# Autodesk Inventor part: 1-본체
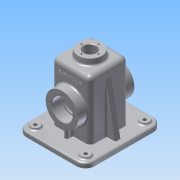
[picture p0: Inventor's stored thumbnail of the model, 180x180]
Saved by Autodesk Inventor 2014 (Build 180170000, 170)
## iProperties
Created: 2016-06
Part Number: 1-본체
Material: 알루미늄 6061
Document SubType Name: Modeling
Designer: Administrator
Density: 2.71 g/cm^3
Appearance: 알루미늄 - 평지
Mass: 812.786 g
Surface Area: 906.873 cm^2
Volume: 299.921 cm^3
Author: Administrator
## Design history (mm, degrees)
sketch "스케치1"
  geometry: L1 (57.5, -65)-(-57.5, -65); L2 (-57.5, -65)-(-57.5, 65); L3 (-57.5, 65)-(57.5, 65); L4 (57.5, 65)-(57.5, -65); L5 (57.5, -65)-(-57.5, 65); L6 (-57.5, -65)-(57.5, 65); 3 further points
  constraints: 12 end point, 3 midpoint, 2 parallel, 1 coincident, 1 horizontal, 1 perpendicular
  dimensions: "d0" = 115 distance of L2.end L3.end; "d1" = 130 distance of L1.end L2.end
extrude "돌출1" new body sketch "스케치1" distance "d2" = 8; taper "d3" = 0 deg
sketch "스케치2"
  geometry: L1 (52.5, 60)-(-52.5, 60); L2 (-52.5, 60)-(-52.5, -60); L3 (-52.5, -60)-(52.5, -60); L4 (52.5, -60)-(52.5, 60); L5 (52.5, 60)-(-52.5, -60); L6 (-52.5, 60)-(52.5, -60); 1 further point
  constraints: 12 end point, 2 midpoint, 2 parallel, 1 horizontal, 1 perpendicular
  dimensions: "d4" = 105 distance of L3.end L2.end; "d5" = 120 distance of L2.end L1.end
extrude "돌출2" join sketch "스케치2" distance "d6" = 2; taper "d7" = 0 deg
fillet "모깎기1" dims "d8" = 15, "d9" = 10
sketch "스케치3"
  geometry: L1 (32.5, 32.5)-(-32.5, 32.5); L2 (-32.5, 32.5)-(-32.5, -32.5); L3 (-32.5, -32.5)-(32.5, -32.5); L4 (32.5, -32.5)-(32.5, 32.5); L5 (32.5, 32.5)-(-32.5, -32.5); L6 (-32.5, 32.5)-(32.5, -32.5); 1 further point
  constraints: 12 end point, 2 midpoint, 2 parallel, 1 horizontal, 1 perpendicular
  dimensions: "d10" = 65 distance of L3.end L2.end; "d11" = 65 distance of L2.end L1.end
extrude "돌출3" join sketch "스케치3" distance "d12" = 100; taper "d13" = 0 deg
node "작업 평면1"
sketch "스케치5"
  geometry: C1 r 20 at (0, 0); 1 further point
  constraints: 1 centre point, 1 coincident
  dimensions: "d16" = 40 diameter of C1
extrude "돌출4" join sketch "스케치5" distance "d17" = 10; taper "d18" = 5 deg
sketch "스케치7"
  geometry: L1 (27.5, 27.5)-(-27.5, 27.5); L2 (-27.5, 27.5)-(-27.5, -27.5); L3 (-27.5, -27.5)-(27.5, -27.5); L4 (27.5, -27.5)-(27.5, 27.5); L5 (27.5, 27.5)-(-27.5, -27.5); L6 (-27.5, 27.5)-(27.5, -27.5); 3 further points
  constraints: 12 end point, 3 midpoint, 2 parallel, 1 coincident, 1 horizontal, 1 perpendicular
  dimensions: "d19" = 55 distance of L3.end L2.end; "d20" = 55 distance of L2.end L1.end
extrude "돌출5" cut sketch "스케치7" distance "d21" = 105; taper "d22" = 0 deg
sketch "스케치9"
  geometry: C1 r 7.5 at (-42.5, 50); A1 r 15 centre (-42.5, 50) between (-42.5, 65) and (-57.5, 50) reference; 1 further point
  constraints: 1 centre point, 1 coincident
  dimensions: "d23" = 15 diameter of C1
extrude "돌출6" join sketch "스케치9" distance "d24" = 3; taper "d25" = 0 deg
sketch "스케치10"
  geometry: C1 r 7.5 at (0, 0) reference; C2 r 3 at (0, 0); 1 further point
  constraints: 1 centre point, 1 coincident
  dimensions: "d26" = 6 diameter of C2
extrude "돌출7" cut sketch "스케치10" distance "d27" = 20; taper "d28" = 0 deg
fillet "모깎기2" dims "d29" = 3
fillet "모깎기3" dims "d37" = 3, "d73" = 3, "d74" = 3
sketch "스케치12"
  geometry: L1 (0, 100)-(65, 100) reference; L2 (85, -10)-(75, -10) reference; C1 r 27.5 at (32.5, 45); 2 further points
  constraints: 1 centre point, 1 midpoint, 1 vertical alignment
  dimensions: "d40" = 55 diameter of C1; "d41" = 55 distance from line of L2 C1.centre
extrude "돌출8" join sketch "스케치12" distance "d42" = 15; taper "d43" = 0 deg
hole "구멍1" diameter "d46" = 30; stored, may be unused: countersink angle "d50" = 90 deg, drill point angle "d52" = 118 deg; dims "d44" = 10, "d45" = 10, "d47" = 6, "d48" = 35, "d49" = 17, "d51" = 20
sketch "스케치14"
  geometry: C1 r 17.5 at (0, 0) reference; 2 further points
  constraints: 1 vertical alignment
  dimensions: "d53" = 21 distance of C1.centre point (0, 21)
hole "구멍2" sketch "스케치14" at (0, 21) diameter "d54" = 3.242; stored, may be unused: countersink angle "d58" = 90 deg, drill point angle "d60" = 118 deg; dims "d55" = 8, "d56" = 35, "d57" = 17, "d59" = 10
chamfer "모따기1" distance "d64" = 1; stored, may be unused: second distance "d65" = 2, angle "d66" = 45 deg
fillet "모깎기4" dims "d67" = 0.3
fillet "모깎기5" dims "d68" = 8
fillet "모깎기6" dims "d69" = 3
fillet "모깎기7" dims "d70" = 8, "d71" = 3
fillet "모깎기8" dims "d72" = 8
sketch "스케치15"
  geometry: C1 r 20 at (0, 0) reference; C2 r 10.5 at (0, 0)
  constraints: 1 centre point, 1 coincident
  dimensions: "d75" = 21 diameter of C2
extrude "돌출9" cut sketch "스케치15" distance "d76" = 30; taper "d77" = 0 deg
sketch "스케치16"
  geometry: C1 r 10.5 at (0, 0) reference; 1 further point
  constraints: 1 vertical alignment
  dimensions: "d78" = 14.5 distance of C1.centre point (0, 14.5)
hole "구멍3" sketch "스케치16" at (0, 14.5) diameter "d79" = 2.459; stored, may be unused: countersink angle "d83" = 90 deg, drill point angle "d85" = 118 deg; dims "d80" = 7, "d81" = 35, "d82" = 17, "d84" = 9
sketch "스케치18"
  geometry: L1 (-27.5, 100)-(-27.5, -2) reference; L2 (-27.5, -2)-(-52.5, -2) reference; L3 (-52.5, -2)-(-52.5, 0) reference; L4 (-52.5, 0)-(-57.5, 0) reference; L5 (-57.5, 0)-(-57.5, 8) reference; L6 (-57.5, 8)-(-32.5, 8) reference; L7 (-32.5, 8)-(-32.5, 100) reference; L8 (-24.5, 108)-(-23.624, 108) reference; L9 (-20.635, 110.739)-(-20, 118) reference; L10 (-20, 118)-(-15.73, 118) reference; L11 (-15.73, 118)-(-15.73, 109) reference; L12 (-15.73, 109)-(-14.5, 108.261) reference; L13 (-14.5, 108.261)-(-13.271, 109) reference; L14 (-13.271, 109)-(-13.271, 118) reference; L15 (-13.271, 118)-(-10.5, 118) reference; L16 (-10.5, 118)-(-10.5, 103) reference; L17 (-10.5, 103)-(-24.5, 103) reference; L18 (24.5, 103)-(10.5, 103) reference; L19 (10.5, 103)-(10.5, 118) reference; L20 (10.5, 118)-(13.271, 118) reference; L21 (13.271, 118)-(13.271, 109) reference; L22 (13.271, 109)-(14.5, 108.261) reference; L23 (14.5, 108.261)-(15.73, 109) reference; L24 (15.73, 109)-(15.73, 118) reference; L25 (15.73, 118)-(20, 118) reference; L26 (20, 118)-(20.635, 110.739) reference; L27 (23.624, 108)-(24.5, 108) reference; L28 (32.5, 100)-(32.5, 8) reference; L29 (32.5, 8)-(57.5, 8) reference; L30 (57.5, 8)-(57.5, 0) reference; L31 (57.5, 0)-(52.5, 0) reference; L32 (52.5, 0)-(52.5, -2) reference; L33 (52.5, -2)-(27.5, -2) reference; L34 (27.5, -2)-(27.5, 100) reference; L35 (-32, 8)-(-53, 8) reference; L36 (-47.5, 8)-(-32.5, 93.069); L37 (-32.5, 8)-(-32.5, 100) reference; A1 r 3 centre (-24.5, 100) between (-24.5, 103) and (-27.5, 100) reference; A2 r 8 centre (-24.5, 100) between (-24.5, 108) and (-32.5, 100) reference; A3 r 3 centre (-23.624, 111) between (-23.624, 108) and (-20.635, 110.739) reference; A4 r 3 centre (24.5, 100) between (27.5, 100) and (24.5, 103) reference; A5 r 3 centre (23.624, 111) between (20.635, 110.739) and (23.624, 108) reference; A6 r 8 centre (24.5, 100) between (32.5, 100) and (24.5, 108) reference; 1 further point
  constraints: 2 end point, 2 point on line
  dimensions: "d95" = 10 distance from line of L5 L36.start; "d96" = 10 deg angle of L5 L36
extrude "돌출11" join sketch "스케치18" stored distance "d97" = 10; taper "d98" = 0 deg
sketch "스케치19"
  geometry: L1 (24.5, 103)-(10.5, 103) reference; L2 (10.5, 103)-(10.5, 118) reference; L3 (10.5, 118)-(13.271, 118) reference; L4 (13.271, 118)-(13.271, 109) reference; L5 (13.271, 109)-(14.5, 108.261) reference; L6 (14.5, 108.261)-(15.73, 109) reference; L7 (15.73, 109)-(15.73, 118) reference; L8 (15.73, 118)-(20, 118) reference; L9 (20, 118)-(20.635, 110.739) reference; L10 (23.624, 108)-(24.5, 108) reference; L11 (32.5, 100)-(32.5, 83.5) reference; L12 (35.5, 80.5)-(47.5, 80.5) reference; L13 (47.5, 80.5)-(47.5, 75.621) reference; L14 (47.5, 75.621)-(37.5, 75.621) reference; L15 (37.5, 75.621)-(36.526, 74) reference; L16 (36.526, 74)-(37.5, 72.379) reference; L17 (37.5, 72.379)-(47.5, 72.379) reference; L18 (47.5, 72.379)-(47.5, 71.5) reference; L19 (47.5, 71.5)-(46.5, 70.5) reference; L20 (46.5, 70.5)-(30.8, 70.5) reference; L21 (30.5, 70.2)-(30.5, 68) reference; L22 (30.5, 68)-(27.5, 68) reference; L23 (27.5, 68)-(27.5, 100) reference; L24 (-27.5, 100)-(-27.5, 68) reference; L25 (-27.5, 68)-(-30.5, 68) reference; L26 (-30.5, 68)-(-30.5, 70.2) reference; L27 (-30.8, 70.5)-(-46.5, 70.5) reference; L28 (-46.5, 70.5)-(-47.5, 71.5) reference; L29 (-47.5, 71.5)-(-47.5, 72.379) reference; L30 (-47.5, 72.379)-(-37.5, 72.379) reference; L31 (-37.5, 72.379)-(-36.526, 74) reference; L32 (-36.526, 74)-(-37.5, 75.621) reference; L33 (-37.5, 75.621)-(-47.5, 75.621) reference; L34 (-47.5, 75.621)-(-47.5, 80.5) reference; L35 (-47.5, 80.5)-(-35.5, 80.5) reference; L36 (-32.5, 83.5)-(-32.5, 100) reference; L37 (-24.5, 108)-(-23.624, 108) reference; L38 (-20.635, 110.739)-(-20, 118) reference; L39 (-20, 118)-(-15.73, 118) reference; L40 (-15.73, 118)-(-15.73, 109) reference; L41 (-15.73, 109)-(-14.5, 108.261) reference; L42 (-14.5, 108.261)-(-13.271, 109) reference; L43 (-13.271, 109)-(-13.271, 118) reference; L44 (-13.271, 118)-(-10.5, 118) reference; L45 (-10.5, 118)-(-10.5, 103) reference; L46 (-10.5, 103)-(-24.5, 103) reference; L47 (-60, -2)-(-60, 0) reference; L48 (-60, 0)-(-65, 0) reference; L49 (-65, 0)-(-65, 8) reference; L50 (-65, 8)-(-32.5, 8) reference; L51 (-32.5, 8)-(-32.5, 22.5) reference; L52 (-35.5, 25.5)-(-47.5, 25.5) reference; L53 (-47.5, 25.5)-(-47.5, 30.379) reference; L54 (-47.5, 30.379)-(-37.5, 30.379) reference; L55 (-37.5, 30.379)-(-36.526, 32) reference; L56 (-36.526, 32)-(-37.5, 33.621) reference; L57 (-37.5, 33.621)-(-47.5, 33.621) reference; L58 (-47.5, 33.621)-(-47.5, 34.5) reference; L59 (-47.5, 34.5)-(-46.5, 35.5) reference; L60 (-46.5, 35.5)-(-30.8, 35.5) reference; L61 (-30.5, 35.8)-(-30.5, 38) reference; L62 (-30.5, 38)-(-27.5, 38) reference; L63 (-27.5, 38)-(-27.5, -2) reference; L64 (-27.5, -2)-(-60, -2) reference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; A1 r 3 centre (24.5, 100) between (27.5, 100) and (24.5, 103) reference; A2 r 3 centre (23.624, 111) between (20.635, 110.739) and (23.624, 108) reference; A3 r 8 centre (24.5, 100) between (32.5, 100) and (24.5, 108) reference; A4 r 3 centre (35.5, 83.5) between (32.5, 83.5) and (35.5, 80.5) reference; A5 r 0.3 centre (30.8, 70.2) between (30.8, 70.5) and (30.5, 70.2) reference; A6 r 3 centre (-24.5, 100) between (-24.5, 103) and (-27.5, 100) reference; A7 r 0.3 centre (-30.8, 70.2) between (-30.5, 70.2) and (-30.8, 70.5) reference; A8 r 3 centre (-35.5, 83.5) between (-35.5, 80.5) and (-32.5, 83.5) reference; A9 r 8 centre (-24.5, 100) between (-24.5, 108) and (-32.5, 100) reference; A10 r 3 centre (-23.624, 111) between (-23.624, 108) and (-20.635, 110.739) reference; A11 r 3 centre (-35.5, 22.5) between (-32.5, 22.5) and (-35.5, 25.5) reference; A12 r 0.3 centre (-30.8, 35.8) between (-30.8, 35.5) and (-30.5, 35.8) reference; A13 r 0.3 centre (30.8, 35.8) between (30.5, 35.8) and (30.8, 35.5) reference; A14 r 3 centre (35.5, 22.5) between (35.5, 25.5) and (32.5, 22.5) reference; 1 further point
  constraints: 8 end point, 2 parallel, 1 collinear, 1 perpendicular, 1 point on line
  dimensions: "d99" = 20 distance of L84.end L50.end; "d101" = 15 distance between parallel lines of L63 L83
extrude "돌출12" join sketch "스케치19" stored distance "d102" = 6; taper "d103" = 0 deg
fillet "모깎기9" dims "d111" = 2
fillet "모깎기12" dims "d107" = 3
sketch "스케치21"
  geometry: L1 (20, 65)-(-20, 65) reference; A1 r 30.5 centre (0, 0) between (24.5, 18.166) and (-24.5, 18.166) reference; 2 further points
  constraints: 1 vertical alignment, 1 other
  dimensions: "d108" = 26 distance from line of point (0, 39) L1
feature "엠보싱1" sketch "스케치21" dims "d109" = 0.5, "d110" = 0
fillet "모깎기13" dims "d112" = 3
fillet "모깎기14" dims "d113" = 3
chamfer "모따기2" distance "d117" = 1; stored, may be unused: second distance "d118" = 2, angle "d119" = 45 deg
fillet "모깎기19" dims "d121" = 3
fillet "모깎기20" dims "d122" = 3
fillet "모깎기21" dims "d123" = 1
node "솔리드1"
pattern_linear "직사각형 패턴1" dims "d35" = 85
pattern_circular "원형 패턴1" dims angle "d62" = 360 deg
mirror "대칭1"
pattern_circular "원형 패턴2" dims angle "d87" = 360 deg
mirror "대칭3"
mirror "대칭4"
node "절단 모서리 투영2"
node "절단 모서리 투영3"
